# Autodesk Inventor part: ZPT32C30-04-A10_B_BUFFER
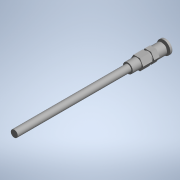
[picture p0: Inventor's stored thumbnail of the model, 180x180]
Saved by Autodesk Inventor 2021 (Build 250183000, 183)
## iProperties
Part Number: ZPT32C30-04-A10_B_BUFFER
Material: Genérico
Catalog Web Link: www.cadenas.de
Description: ZPT_20_32B_BUFFER-Vacuum Pad/Vertical Vacuum Entry With Buffer
Vendor: SMC
Document SubType Name: Modeling
Designer: partserver
Manufacturer: SMC
Mass: 5.31182 g
Surface Area: 38.1936 cm^2
Volume: 5.31182 cm^3
Density: 1 g/cm^3
Appearance: PSOLRGB-192-192-192
Category: PARTsolutions
Company: SMC
PSOL_IDENT_0: {$CADENAS_DATA\23d-libs\smc_jp\vacuum_equipment\vacuum_pad\zp\zpt_b\zpt_20_32_b\parts\zpt_20_32_buff
PSOL_IDENT_1: er_b.prj},217 {VTYP=3D},{NB=ZPT32C30-04-A10_B_BUFFER},{LINA=ZPT32C30-04-A10_B_BUFFER},{NN=ZPT_20_32B
PSOL_IDENT_2: _BUFFER},{DATE=03.02.2021 04:15:19},{GEOMDATE=19.04.2012 02:41:00},{VERSION=},{LINEID=130},{WBVAR=ST
PSOL_IDENT_3: ROKE,PORT},{WBNUMERIC=STROKE}  {NB=ZPT32C30-04-A10_B_BUFFER},{LINA=ZPT32C30-04-A10_B_BUFFER},{KT=DUM
PSOL_IDENT_4: MY},{DIAMETER=32},{PAD=(C) Flat with ribs},{PADX=C},{STROKE=30},{PORT=04},{MOUNT=(A10) M10x1 (Male t
PSOL_IDENT_5: hread)},{ORDER=ZPT32C30-04-A10},{TIFX=U2},{A=32.000},{B=35.000},{C=14.500},{D=23.500},{Y=2.300},{E=5
PSOL_IDENT_6: 5},{F=133},{G=51},{FB5=0},{F04=133},{FN6U6=121}
NB: ZPT32C30-04-A10_B_BUFFER
NN: ZPT_20_32B_BUFFER
NT: Vacuum Pad/Vertical Vacuum Entry With Buffer
NBSYN: $ORDER._B_BUFFER
LINA: ZPT32C30-04-A10_B_BUFFER
CATALOG: SMC (JP
DIAMETER: 32
PAD: (C) Flat with ribs
STROKE: 30
PORT: (04) dia 4 tube (One-touch fitting)
MOUNT: (A10) M10x1 (Male thread)
A: 32
B: 35
C: 14.5
D: 23.5
Y: 2.3
E: 55
F: 133
G: 51
SUPPLIER: SMC
ARTICLENO: ZPT32C30-04-A10_B_BUFFER
BOMINFO: ZPT32C30-04-A10_B_BUFFER
CREATOR: CADENAS GmbH
Title: ZPT32C30-04-A10_B_BUFFER
Author: Cadenas PARTsolutions
Comments: Vacuum Pad/Vertical Vacuum Entry With Buffer
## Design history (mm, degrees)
sketch "Sketch_1"
  geometry: L1 (0, 25)-(0, 106); L2 (0, 106)-(2.479, 106); L3 (2.479, 106)-(2.479, 25); L4 (2.479, 25)-(0, 25); L5 (0, 25)-(0, 106)
  constraints: 10 end point, 1 perpendicular, 1 point on line, 1 vertical
revolve "Revolution1" sketch "Sketch_1" stored, may be unused: angle "d0" = 360 deg
sketch "Sketch_2"
  geometry: L1 (0, 106)-(0, 112.35); L2 (0, 112.35)-(3.5, 112.35); L3 (3.5, 112.35)-(3.5, 106); L4 (3.5, 106)-(0, 106); L5 (0, 106)-(0, 112.35)
  constraints: 10 end point
revolve "Revolution2" sketch "Sketch_2" stored, may be unused: angle "d3" = 360 deg
sketch "Sketch_3"
  geometry: L1 (-4.619, 0)-(-2.309, -4); L2 (-2.309, -4)-(2.309, -4); L3 (2.309, -4)-(4.619, 0); L4 (4.619, 0)-(2.309, 4); L5 (2.309, 4)-(-2.309, 4); L6 (-2.309, 4)-(-4.619, 0)
  constraints: 12 end point
extrude "Extrusion1" join sketch "Sketch_3" distance "d4" = 6.65; taper "d5" = 0 deg
sketch "Sketch_8"
  geometry: L1 (0, 119)-(0, 120.3); L2 (0, 120.3)-(3.45, 120.3); L3 (3.45, 120.3)-(3.45, 119); L4 (3.45, 119)-(0, 119); L5 (0, 119)-(0, 120.3)
  constraints: 10 end point
revolve "Revolution3" sketch "Sketch_8" stored, may be unused: angle "d6" = 360 deg
sketch "Sketch_10"
  geometry: L1 (-4.561, 0)-(-2.281, -3.95); L2 (-2.281, -3.95)-(2.281, -3.95); L3 (2.281, -3.95)-(4.561, 0); L4 (4.561, 0)-(2.281, 3.95); L5 (2.281, 3.95)-(-2.281, 3.95); L6 (-2.281, 3.95)-(-4.561, 0)
  constraints: 12 end point
extrude "Extrusion2" join sketch "Sketch_10" distance "d7" = 3.8; taper "d8" = 0 deg
sketch "Sketch_11"
  geometry: L1 (0, 124.1)-(0, 133); L2 (0, 133)-(4.75, 133); L3 (4.75, 133)-(4.75, 131.5); L4 (4.75, 131.5)-(2.05, 131.5); L5 (2.05, 131.5)-(2.05, 130); L6 (2.05, 130)-(3.95, 130); L7 (3.95, 130)-(3.95, 124.1); L8 (3.95, 124.1)-(0, 124.1); L9 (0, 124.1)-(0, 133)
  constraints: 18 end point
revolve "Revolution4" sketch "Sketch_11" stored, may be unused: angle "d9" = 360 deg
sketch "Sketch_12"
  geometry: L1 (0, 45)-(0, 133); L2 (0, 133)-(2, 133); L3 (2, 133)-(2, 119); L4 (2, 119)-(1.621, 118.621); L5 (1.621, 118.621)-(1.621, 115); L6 (1.621, 115)-(1.25, 114.786); L7 (1.25, 114.786)-(1.25, 45); L8 (1.25, 45)-(0, 45); L9 (0, 45)-(0, 133)
  constraints: 18 end point
revolve "Revolution5" sketch "Sketch_12" stored, may be unused: angle "d10" = 360 deg
thread "Thread2" dims "d11" = 3.621, "d12" = 0
node "NUT_XY"
node "NUT_YZ"
node "NUT_ZX"
node "NUT_X"
node "NUT_Y"
node "NUT_Z"
node "NUT_Center"
node "NUT2_XY"
node "NUT2_YZ"
node "NUT2_ZX"
node "NUT2_X"
node "NUT2_Y"
node "NUT2_Z"
node "NUT2_Center"
node "adapter_XY"
node "adapter_YZ"
node "adapter_ZX"
node "adapter_X"
node "adapter_Y"
node "adapter_Z"
node "adapter_Center"
body "Solid1"
other parameters: "d13" = 0
